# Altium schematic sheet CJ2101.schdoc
size 127 x 101 mm
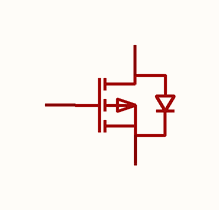
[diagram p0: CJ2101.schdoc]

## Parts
Q?  cj2101  [SOT-323_L2.0-W1.3-P1.30-LS2.1-BR]  (value not drawn)

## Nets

Not connected (* = marked no-connect by the designer): Q? 1(G) 2(S) 3(D)

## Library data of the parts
Q? = cj2101: 数量:1个P沟道;漏源电压(Vdss):20V;连续漏极电流(Id):1.4A;导通电阻(RDS(on)):210mΩ@1.8V;耗散功率(Pd):290mW;阈值电压(Vgs(th)):450mV;; Manufacturer: CJ(江苏长电/长晶); AddInBom: yes; ModelId: 6e43428e1fa34e53bcc36d788ead2567; ModelName: SOT-323_L2.0-W1.3-H1.0-LS2.1-P1.30; ModelTransform: 78.74,82.677,0,90,0,0,0,0,0; Number: 1个P沟道; Drain to Source Voltage: 20V; Current - Continuous Drain(Id): 1.4A; Pd - Power Dissipation: 290mW; Gate Threshold Voltage (Vgs(th)): 450mV; Input Capacitance(Ciss): 640pF; Reverse Transfer Capacitance (Crss@Vds): 82pF; Type: P沟道; Output Capacitance(Coss): 120pF; Vgs: ±8V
